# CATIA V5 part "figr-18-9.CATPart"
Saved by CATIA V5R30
Part number: Part1
Bounding box of the stored display mesh (mm): x -125 to 125, y -70.235 to 70.235, z 0 to 30
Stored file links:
  D:\PROJECTS\CATIA V56R 2020\Resources\Parts File\c18_catia_v6_6r2020_prt\figr-18-9.CATPart
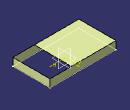
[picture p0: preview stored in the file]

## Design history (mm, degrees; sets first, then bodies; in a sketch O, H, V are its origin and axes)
Body1 (main body)
  Sketch1 on xy-plane, origin (0, 0, 0), H (1, 0, 0), V (0, 1, 0)
    line L1 (125, 70.235) -> (125, -70.235)
    line L2 (125, -70.235) -> (-125, -70.235)
    line L3 (-125, -70.235) -> (-125, 70.235)
    line L4 (-125, 70.235) -> (125, 70.235)
    length L2 = 250
    length L3 = 140.47
    vertical: L1 V, L3 V
    horizontal: L2 H, L4 H
    equidistance: L1 L3 O, L2 L4 O
  Extrude1: Element1 Sketch1, Lim1 30, Lim2 0
  DatumSurface1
